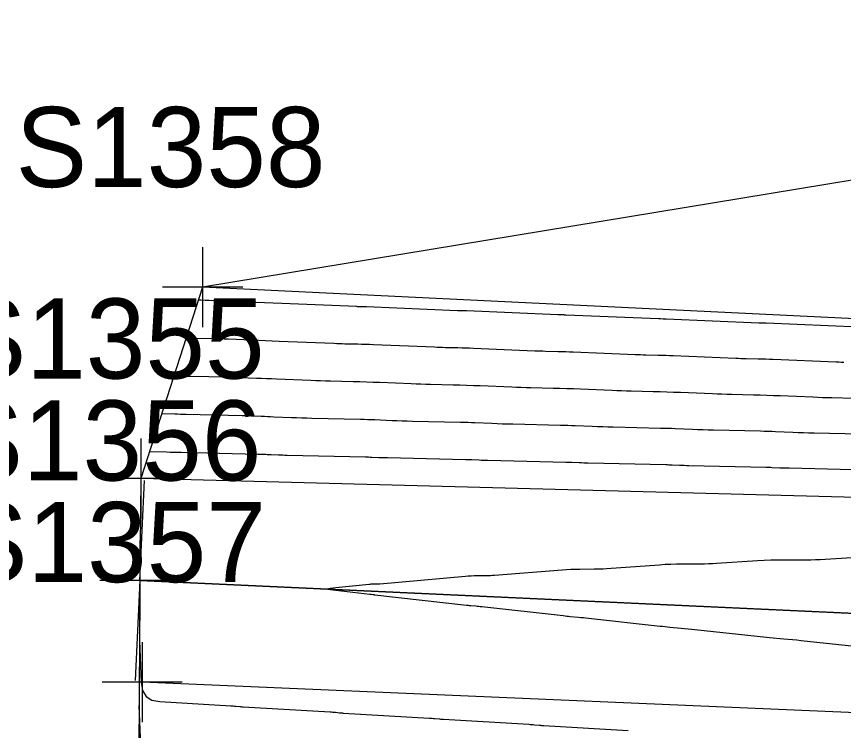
# Model space of a CAD drawing. Extents: x 816928 to 825690, y 436959 to 448212.
# Drawn here: x 818704.36 to 818745.64, y 445193.57 to 445229.23 of the extents above; entities that cross this region are included whole.
import ezdxf

# ---------------------------------------------------------------- set-up
doc = ezdxf.new("R2010")
doc.units = 0
for name, color, linetype in [('DESIGN - SCRATCH - User 1', 7, 'Continuous'), ('SURVEY - CONTOURS - Index with Text', 7, 'Continuous'), ('SURVEY - CONTOURS - Intermediate with optional Text', 7, 'Continuous'), ('SURVEY - DRAINAGE - Bridge Hydraulic Data - Points - Locators', 7, 'Continuous'), ('SURVEY - DRAINAGE - Bridge Hydraulic Data - Points - Numbers', 7, 'Continuous'), ('SURVEY - DRAINAGE - Bridge Hydraulic Data with Text', 7, 'Continuous'), ('SURVEY - DRAINAGE - Natural Features', 7, 'Continuous'), ('SURVEY - DRAINAGE - Natural Features - Points - Locators', 7, 'Continuous'), ('SURVEY - DRAINAGE - Natural Features - Points - Numbers', 7, 'Continuous')]:
    doc.layers.add(name, color=color, linetype=linetype)

msp = doc.modelspace()

# ---------------------------------------------------------------- linework, layer by layer
at = {"layer": 'DESIGN - SCRATCH - User 1'}
msp.add_lwpolyline([(818977.048, 445516.063), (818962.977, 445468.048), (818911.357, 445419.447), (818895.02, 445347.602), (818900.539, 445320.739), (818847.351, 445272.301), (818844.312, 445271.58), (818842.262, 445267.021), (818783.743, 445227.107), (818781.632, 445226.923), (818713.653, 445215.711), (818710.566, 445206.148), (818710.514, 445201.057), (818710.411, 445183.877), (818720.129, 445113.759), (818716.658, 445105.767), (818715.423, 445100.924), (818715.142, 445099.822), (818745.74, 445051.115)], dxfattribs=at)
at = {"layer": 'SURVEY - CONTOURS - Index with Text'}
for points in [[(818746.761, 445206.577), (818742.926, 445206.665), (818742.811, 445206.668), (818742.695, 445206.671), (818742.58, 445206.675), (818742.465, 445206.68), (818742.089, 445206.696), (818742.008, 445206.699), (818741.927, 445206.702), (818741.847, 445206.704), (818741.766, 445206.706), (818737.914, 445206.794), (818737.801, 445206.797), (818737.687, 445206.8), (818737.574, 445206.804), (818737.46, 445206.809), (818737.089, 445206.824), (818737.01, 445206.828), (818736.93, 445206.83), (818736.851, 445206.833), (818736.771, 445206.835), (818732.903, 445206.923), (818732.791, 445206.926), (818732.679, 445206.929), (818732.567, 445206.933), (818732.456, 445206.938), (818732.09, 445206.953), (818732.012, 445206.956), (818731.933, 445206.959), (818731.855, 445206.961), (818731.777, 445206.963), (818727.892, 445207.052), (818727.782, 445207.055), (818727.671, 445207.058), (818727.561, 445207.062), (818727.451, 445207.066), (818727.091, 445207.081), (818727.014, 445207.084), (818726.936, 445207.087), (818726.859, 445207.089), (818726.782, 445207.091), (818722.881, 445207.18), (818722.772, 445207.183), (818722.663, 445207.186), (818722.555, 445207.19), (818722.446, 445207.194), (818722.091, 445207.209), (818722.015, 445207.212), (818721.939, 445207.215), (818721.863, 445207.217), (818721.787, 445207.219), (818717.869, 445207.308), (818717.762, 445207.311), (818717.655, 445207.314), (818717.548, 445207.317), (818717.441, 445207.322), (818717.073, 445207.337), (818717.008, 445207.34), (818716.942, 445207.342), (818716.877, 445207.345), (818716.811, 445207.348), (818716.598, 445207.357), (818716.552, 445207.359), (818716.506, 445207.36), (818716.46, 445207.362), (818716.415, 445207.363), (818712.58, 445207.45), (818712.398, 445207.454), (818712.215, 445207.458), (818712.032, 445207.462), (818711.85, 445207.466), (818710.998, 445207.486)], [(818710.496, 445198.057), (818710.579, 445195.962), (818710.651, 445195.565), (818710.83, 445195.275), (818711.117, 445195.09), (818711.512, 445195.011), (818715.062, 445194.805), (818715.123, 445194.801), (818715.184, 445194.797), (818715.245, 445194.792), (818715.306, 445194.786), (818715.505, 445194.766), (818715.547, 445194.762), (818715.59, 445194.758), (818715.633, 445194.755), (818715.675, 445194.753), (818720.018, 445194.499), (818720.083, 445194.495), (818720.149, 445194.49), (818720.214, 445194.485), (818720.279, 445194.479), (818720.491, 445194.457), (818720.536, 445194.453), (818720.582, 445194.449), (818720.627, 445194.446), (818720.673, 445194.443), (818724.975, 445194.191), (818725.044, 445194.186), (818725.114, 445194.181), (818725.183, 445194.176), (818725.251, 445194.169), (818725.477, 445194.147), (818725.525, 445194.142), (818725.573, 445194.138), (818725.622, 445194.134), (818725.67, 445194.131), (818729.933, 445193.88), (818730.006, 445193.876), (818730.079, 445193.87), (818730.152, 445193.864), (818730.225, 445193.857), (818730.462, 445193.834), (818730.513, 445193.829), (818730.564, 445193.825), (818730.616, 445193.821), (818730.667, 445193.818), (818734.891, 445193.568)]]:
    msp.add_lwpolyline(points, dxfattribs=at)
at = {"layer": 'SURVEY - CONTOURS - Intermediate with optional Text'}
for points in [[(818746.43, 445213.714), (818741.78, 445213.91), (818741.744, 445213.911), (818741.708, 445213.912), (818741.672, 445213.914), (818741.635, 445213.914), (818741.517, 445213.917), (818741.491, 445213.918), (818741.466, 445213.919), (818741.441, 445213.919), (818741.415, 445213.92), (818736.792, 445214.114), (818736.754, 445214.116), (818736.715, 445214.117), (818736.676, 445214.118), (818736.637, 445214.119), (818736.51, 445214.122), (818736.482, 445214.123), (818736.455, 445214.124), (818736.428, 445214.125), (818736.401, 445214.126), (818731.805, 445214.318), (818731.763, 445214.32), (818731.721, 445214.321), (818731.68, 445214.323), (818731.638, 445214.324), (818731.502, 445214.327), (818731.473, 445214.328), (818731.444, 445214.328), (818731.415, 445214.329), (818731.386, 445214.331), (818726.817, 445214.522), (818726.772, 445214.523), (818726.728, 445214.525), (818726.684, 445214.526), (818726.64, 445214.527), (818726.495, 445214.531), (818726.464, 445214.531), (818726.433, 445214.532), (818726.402, 445214.533), (818726.371, 445214.535), (818721.828, 445214.724), (818721.782, 445214.726), (818721.735, 445214.728), (818721.688, 445214.729), (818721.641, 445214.73), (818721.488, 445214.734), (818721.455, 445214.734), (818721.422, 445214.735), (818721.389, 445214.737), (818721.357, 445214.738), (818717.6, 445214.894), (818717.171, 445214.912), (818716.741, 445214.93), (818716.312, 445214.948), (818715.883, 445214.966), (818713.981, 445215.045), (818713.93, 445215.047), (818713.879, 445215.049), (818713.828, 445215.05), (818713.777, 445215.052), (818713.568, 445215.057), (818713.554, 445215.057), (818713.539, 445215.057), (818713.525, 445215.057), (818713.51, 445215.058), (818713.443, 445215.059)], [(818745.66, 445211.949), (818745.532, 445211.953), (818745.403, 445211.958), (818745.274, 445211.963), (818742.135, 445212.095), (818741.949, 445212.102), (818741.763, 445212.108), (818741.577, 445212.114), (818741.39, 445212.119), (818740.782, 445212.133), (818740.652, 445212.136), (818740.521, 445212.14), (818740.391, 445212.144), (818740.261, 445212.15), (818737.146, 445212.28), (818736.957, 445212.288), (818736.769, 445212.294), (818736.58, 445212.3), (818736.391, 445212.305), (818735.775, 445212.319), (818735.643, 445212.322), (818735.511, 445212.326), (818735.379, 445212.331), (818735.247, 445212.336), (818732.156, 445212.465), (818731.965, 445212.473), (818731.774, 445212.479), (818731.583, 445212.485), (818731.392, 445212.49), (818730.768, 445212.504), (818730.635, 445212.508), (818730.501, 445212.512), (818730.367, 445212.516), (818730.234, 445212.521), (818727.167, 445212.65), (818726.973, 445212.657), (818726.78, 445212.664), (818726.587, 445212.67), (818726.393, 445212.675), (818725.762, 445212.689), (818725.626, 445212.692), (818725.491, 445212.697), (818725.355, 445212.701), (818725.22, 445212.707), (818722.177, 445212.834), (818721.982, 445212.841), (818721.786, 445212.848), (818721.59, 445212.854), (818721.394, 445212.859), (818720.755, 445212.873), (818720.618, 445212.877), (818720.481, 445212.881), (818720.344, 445212.886), (818720.207, 445212.891), (818717.468, 445213.005), (818717.13, 445213.019), (818716.792, 445213.033), (818716.453, 445213.047), (818716.115, 445213.061), (818714.934, 445213.111), (818714.735, 445213.118), (818714.536, 445213.125), (818714.337, 445213.131), (818714.138, 445213.136), (818713.321, 445213.155), (818713.265, 445213.156), (818713.208, 445213.157), (818713.152, 445213.159), (818713.095, 445213.16), (818712.832, 445213.166)], [(818746.145, 445210.155), (818745.054, 445210.181), (818744.82, 445210.186), (818744.586, 445210.193), (818744.353, 445210.202), (818744.119, 445210.211), (818742.489, 445210.279), (818742.153, 445210.293), (818741.817, 445210.304), (818741.481, 445210.314), (818741.145, 445210.323), (818740.047, 445210.348), (818739.812, 445210.354), (818739.577, 445210.361), (818739.342, 445210.369), (818739.106, 445210.379), (818737.499, 445210.446), (818737.161, 445210.459), (818736.822, 445210.471), (818736.484, 445210.481), (818736.146, 445210.49), (818735.041, 445210.515), (818734.804, 445210.521), (818734.567, 445210.528), (818734.331, 445210.536), (818734.094, 445210.546), (818732.507, 445210.612), (818732.167, 445210.626), (818731.827, 445210.637), (818731.487, 445210.648), (818731.147, 445210.656), (818730.034, 445210.682), (818729.796, 445210.688), (818729.558, 445210.695), (818729.319, 445210.703), (818729.081, 445210.712), (818727.507, 445210.778), (818727.17, 445210.792), (818726.832, 445210.803), (818726.495, 445210.813), (818726.157, 445210.822), (818725.031, 445210.847), (818724.79, 445210.854), (818724.548, 445210.861), (818724.307, 445210.869), (818724.066, 445210.879), (818722.506, 445210.944), (818722.171, 445210.957), (818721.837, 445210.968), (818721.502, 445210.978), (818721.168, 445210.987), (818720.028, 445211.013), (818719.783, 445211.019), (818719.539, 445211.026), (818719.295, 445211.035), (818719.05, 445211.044), (818717.337, 445211.116), (818717.089, 445211.126), (818716.842, 445211.136), (818716.594, 445211.147), (818716.347, 445211.157), (818715.539, 445211.191), (818715.366, 445211.197), (818715.193, 445211.203), (818715.019, 445211.209), (818714.846, 445211.213), (818713.074, 445211.253), (818712.976, 445211.255), (818712.877, 445211.258), (818712.779, 445211.26), (818712.68, 445211.262), (818712.22, 445211.272)], [(818746.494, 445208.365), (818744.172, 445208.418), (818743.906, 445208.425), (818743.641, 445208.433), (818743.376, 445208.442), (818743.11, 445208.453), (818742.244, 445208.489), (818742.058, 445208.497), (818741.872, 445208.503), (818741.687, 445208.509), (818741.501, 445208.513), (818739.159, 445208.567), (818738.895, 445208.574), (818738.632, 445208.582), (818738.369, 445208.591), (818738.105, 445208.601), (818737.245, 445208.637), (818737.061, 445208.645), (818736.876, 445208.651), (818736.692, 445208.657), (818736.508, 445208.661), (818734.146, 445208.715), (818733.885, 445208.722), (818733.623, 445208.73), (818733.362, 445208.739), (818733.1, 445208.749), (818732.246, 445208.785), (818732.063, 445208.792), (818731.88, 445208.798), (818731.697, 445208.804), (818731.514, 445208.808), (818729.134, 445208.863), (818728.874, 445208.869), (818728.615, 445208.877), (818728.355, 445208.886), (818728.095, 445208.896), (818727.248, 445208.932), (818727.066, 445208.939), (818726.884, 445208.945), (818726.702, 445208.951), (818726.521, 445208.955), (818724.121, 445209.01), (818723.864, 445209.016), (818723.606, 445209.024), (818723.348, 445209.033), (818723.091, 445209.043), (818722.249, 445209.078), (818722.069, 445209.085), (818721.888, 445209.092), (818721.708, 445209.097), (818721.527, 445209.102), (818719.109, 445209.157), (818718.853, 445209.163), (818718.597, 445209.171), (818718.341, 445209.18), (818718.086, 445209.19), (818717.205, 445209.226), (818717.048, 445209.233), (818716.892, 445209.239), (818716.736, 445209.246), (818716.579, 445209.252), (818716.068, 445209.274), (818715.959, 445209.278), (818715.849, 445209.282), (818715.74, 445209.285), (818715.63, 445209.288), (818712.827, 445209.351), (818712.687, 445209.355), (818712.546, 445209.358), (818712.405, 445209.361), (818712.265, 445209.364), (818711.609, 445209.379)], [(818746.186, 445197.764), (818743.528, 445198.051), (818743.31, 445198.074), (818743.093, 445198.096), (818742.875, 445198.117), (818742.658, 445198.137), (818741.946, 445198.201), (818741.794, 445198.215), (818741.642, 445198.23), (818741.49, 445198.245), (818741.337, 445198.262), (818738.225, 445198.602), (818738.053, 445198.62), (818737.881, 445198.638), (818737.709, 445198.655), (818737.537, 445198.671), (818736.975, 445198.722), (818736.855, 445198.733), (818736.734, 445198.745), (818736.614, 445198.757), (818736.494, 445198.77), (818732.912, 445199.166), (818732.788, 445199.18), (818732.663, 445199.192), (818732.538, 445199.205), (818732.413, 445199.217), (818732.004, 445199.254), (818731.917, 445199.262), (818731.829, 445199.271), (818731.742, 445199.28), (818731.655, 445199.29), (818727.589, 445199.744), (818727.513, 445199.753), (818727.436, 445199.76), (818727.36, 445199.768), (818727.284, 445199.775), (818727.035, 445199.798), (818726.981, 445199.804), (818726.928, 445199.809), (818726.874, 445199.815), (818726.821, 445199.82), (818722.254, 445200.337), (818722.228, 445200.34), (818722.202, 445200.343), (818722.176, 445200.345), (818722.15, 445200.348), (818722.066, 445200.356), (818722.047, 445200.357), (818722.029, 445200.359), (818722.011, 445200.361), (818721.993, 445200.363), (818720.3, 445200.557), (818720.028, 445200.598), (818719.938, 445200.638), (818720.029, 445200.676), (818720.301, 445200.713), (818721.965, 445200.88), (818722.018, 445200.885), (818722.072, 445200.888), (818722.125, 445200.891), (818722.178, 445200.892), (818722.352, 445200.893), (818722.39, 445200.894), (818722.427, 445200.896), (818722.464, 445200.898), (818722.501, 445200.901), (818726.767, 445201.281), (818726.911, 445201.292), (818727.055, 445201.3), (818727.199, 445201.306), (818727.343, 445201.308), (818727.814, 445201.311), (818727.915, 445201.313), (818728.015, 445201.316), (818728.116, 445201.322), (818728.217, 445201.329), (818731.603, 445201.599), (818731.822, 445201.614), (818732.04, 445201.625), (818732.259, 445201.632), (818732.478, 445201.635), (818733.193, 445201.638), (818733.347, 445201.64), (818733.5, 445201.645), (818733.653, 445201.652), (818733.806, 445201.661), (818736.466, 445201.852), (818736.747, 445201.87), (818737.028, 445201.883), (818737.31, 445201.891), (818737.591, 445201.894), (818738.512, 445201.896), (818738.709, 445201.898), (818738.906, 445201.903), (818739.103, 445201.911), (818739.299, 445201.922), (818741.349, 445202.056), (818741.683, 445202.075), (818742.018, 445202.088), (818742.353, 445202.097), (818742.688, 445202.1), (818743.782, 445202.1), (818744.016, 445202.102), (818744.251, 445202.107), (818744.485, 445202.116), (818744.719, 445202.128), (818746.322, 445202.223)], [(818710.476, 445194.823), (818710.541, 445193.205)]]:
    msp.add_lwpolyline(points, dxfattribs=at)
at = {"layer": 'SURVEY - DRAINAGE - Bridge Hydraulic Data - Points - Locators'}
for p, q in [((818713.653, 445217.711), (818713.653, 445213.711)), ((818715.653, 445215.711), (818711.653, 445215.711)), ((818710.566, 445208.148), (818710.566, 445204.148)), ((818712.566, 445206.148), (818708.566, 445206.148)), ((818710.632, 445197.982), (818710.632, 445193.982)), ((818712.632, 445195.982), (818708.632, 445195.982))]:
    msp.add_line(p, q, dxfattribs=at)
at = {"layer": 'SURVEY - DRAINAGE - Bridge Hydraulic Data with Text'}
for q in [(818710.744, 445206.051), (818710.284, 445196.062), (818757.037, 445198.917)]:
    msp.add_line((818710.514, 445201.057), q, dxfattribs=at)
for points in [[(818808.648, 445229.275), (818781.632, 445226.923), (818761.671, 445213.378), (818713.653, 445215.711)], [(818981.856, 445170.386), (818981.679, 445172.324), (818961.15, 445189.092), (818885.148, 445199.156), (818830.646, 445194.716), (818800.042, 445220.122), (818756.964, 445204.922), (818710.566, 445206.148)], [(818975.535, 445161.489), (818974.654, 445162.222), (818955.542, 445179.169), (818885.6, 445191.376), (818829.741, 445185.211), (818795.23, 445208.399), (818755.569, 445194.059), (818710.632, 445195.982)]]:
    msp.add_lwpolyline(points, dxfattribs=at)
at = {"layer": 'SURVEY - DRAINAGE - Natural Features'}
msp.add_lwpolyline([(818976.92, 445167.021), (818959.968, 445184.233), (818885.355, 445194.671), (818834.683, 445188.997), (818798.356, 445212.301), (818757.037, 445198.917), (818710.514, 445201.057)], dxfattribs=at)
at = {"layer": 'SURVEY - DRAINAGE - Natural Features - Points - Locators'}
for p, q in [((818710.514, 445203.057), (818710.514, 445199.057)), ((818712.514, 445201.057), (818708.514, 445201.057))]:
    msp.add_line(p, q, dxfattribs=at)

# ---------------------------------------------------------------- texts
at = {"layer": 'SURVEY - DRAINAGE - Bridge Hydraulic Data - Points - Numbers'}
for s, p in [('S1358', (818704.318, 445220.711)), ('S1355', (818701.278, 445211.148)), ('S1357', (818701.344, 445200.982))]:
    msp.add_text(s, height=4, dxfattribs=at).set_placement(p)
at = {"layer": 'SURVEY - DRAINAGE - Natural Features - Points - Numbers'}
msp.add_text('S1356', height=4, dxfattribs=at).set_placement((818701.116, 445206.057))

doc.saveas('drawing.dxf')
